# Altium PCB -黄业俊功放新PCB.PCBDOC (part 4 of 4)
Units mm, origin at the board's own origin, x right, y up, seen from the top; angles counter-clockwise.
Board outline 130 x 100.6 mm, 2 copper layers (Top Layer, Bottom Layer); 47 components, 24 nets, 117 pads, 4 vias.
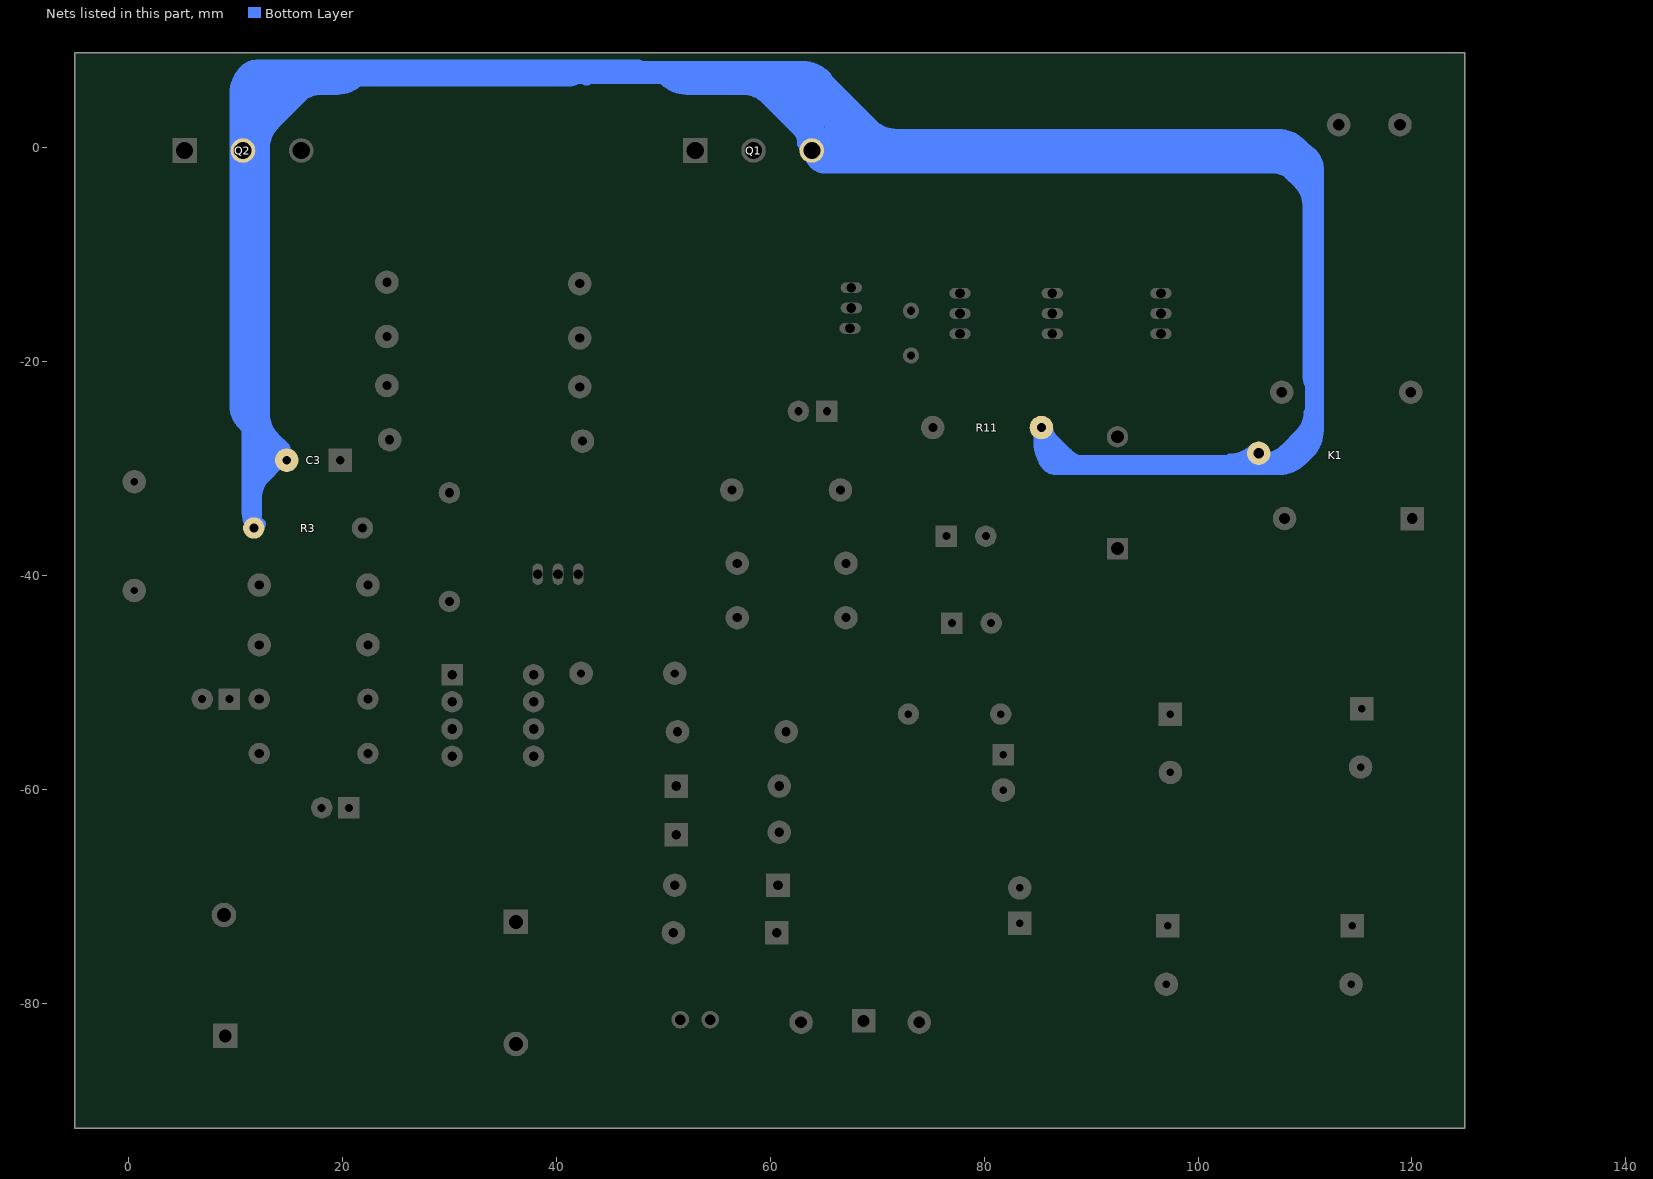
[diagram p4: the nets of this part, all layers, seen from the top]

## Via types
v1: diameter 2.54, hole 0.762, Top Layer to Bottom Layer, 4 vias

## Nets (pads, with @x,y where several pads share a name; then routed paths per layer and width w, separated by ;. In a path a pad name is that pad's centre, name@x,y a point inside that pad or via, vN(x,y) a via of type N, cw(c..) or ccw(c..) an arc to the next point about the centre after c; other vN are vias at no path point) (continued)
OUT: C3.2 K1.3 Q1.3 Q2.2 R3.2 R11.2 | length 1584.2
  Bottom Layer w1: 9.906,-24.13 ccw(c12.359,-24.13) 10.624,-25.864 10.786,-26.026 cw(c8.618,-28.194) 11.684,-28.194 11.684,-29.337 ; Q2.2@9.906,-0.381 10.259,-0.734 cw(c8.351,-2.642) 11.049,-2.642 11.049,-34.154 ccw(c13.217,-34.154) R3.2@11.684,-35.687 ; Q2.2@10.287,-0.381 10.287,-23.539 ccw(c12.021,-23.539) 10.795,-24.765 cw(c9.569,-25.991) 11.303,-25.991 11.303,-31.877 ; Q2.2@10.287,-0.254 10.287,4.69 cw(c12.455,4.69) 10.922,6.223 11.021,6.322 cw(c12.929,4.414) 12.929,7.112 62.001,7.112 cw(c62.001,4.414) 63.909,6.322 cw(c63.058,5.47) 64.262,5.47 Q1.3@64.262,-0.635 ; Q2.2@10.668,0.254 10.668,3.581 cw(c13.366,3.581) 11.458,5.489 11.529,5.56 cw(c13.437,3.652) 13.437,6.35 ; Q2.2@10.922,-0.381 10.922,1.549 cw(c13.62,1.549) 11.712,3.457 13.561,5.306 cw(c15.469,3.398) 15.469,6.096 ; Q2.2@11.049,-0.635 11.049,2.438 cw(c13.747,2.438) 11.839,4.346 13.18,5.687 cw(c15.088,3.779) 15.088,6.477 59.969,6.477 cw(c59.969,3.779) 61.877,5.687 62.583,4.981 cw(c60.675,3.073) 63.373,3.073 63.373,0.815 ccw(c63.807,0.815) 63.5,0.508 63.537,0.471 cw(c63.32,0.254) Q1.3@63.627,0.254 ; Q2.2@11.303,0.254 11.529,0.028 cw(c9.621,-1.88) 12.319,-1.88 12.319,-25.933 ccw(c15.017,-25.933) 13.109,-27.841 13.753,-28.485 ccw(c13.97,-28.268) C3.2@13.97,-28.575 ; Q2.2@11.43,-0.508 11.43,3.327 cw(c14.128,3.327) 12.22,5.235 12.291,5.306 cw(c14.199,3.398) 14.199,6.096 ; 11.557,-26.543 10.804,-25.79 cw(c12.972,-23.622) 9.906,-23.622 9.906,4.318 9.906,5.08 cw(c12.972,5.08) 10.804,7.248 cw(c12.009,6.043) 12.009,7.747 47.572,7.747 cw(c47.572,7.313) 47.879,7.62 62.992,7.62 cw(c62.992,4.554) 65.16,6.722 cw(c64.875,6.437) 65.278,6.437 65.278,3.237 ccw(c67.88,3.237) 66.04,1.397 ccw(c67.266,2.623) 67.266,0.889 107.709,0.889 cw(c107.709,-2.146) 109.855,0 110.258,-0.403 cw(c109.391,-1.27) 110.617,-1.27 ccw(c110.617,-2.19) 109.967,-1.539 ; Q2.2@11.557,0.381 11.557,2.819 cw(c14.255,2.819) 12.347,4.727 13.434,5.814 cw(c15.342,3.906) 15.342,6.604 60.477,6.604 cw(c60.477,3.906) 62.385,5.814 63.091,5.108 cw(c61.183,3.2) 63.881,3.2 Q1.3@63.881,0 ; R3.2@11.684,-35.179 11.684,-31.233 cw(c12.888,-31.233) 12.037,-30.381 cw(c13.945,-32.289) 13.945,-29.591 C3.2@14.351,-29.591 ; 11.684,-30.455 cw(c12.802,-30.455) 12.802,-29.337 C3.2@14.605,-29.337 ; 11.684,-25.781 11.684,-26.521 ccw(c14.189,-26.521) 12.418,-28.293 ccw(c14.326,-26.385) 14.326,-29.083 C3.2@14.478,-29.083 ; Q2.2@11.684,-0.635 11.684,-34.544 ccw(c12.319,-34.544) R3.2@12.319,-35.179 ; R3.2@11.938,-35.306 11.938,-32.741 cw(c14.636,-32.741) 12.728,-30.833 C3.2@13.97,-29.591 ; 11.938,-28.194 12.827,-29.083 ; 12.065,-1.27 12.065,1.016 cw(c15.131,1.016) 12.963,3.184 15.104,5.325 cw(c17.272,3.157) 17.272,6.223 41.065,6.223 ccw(c41.065,7.957) 42.291,6.731 42.586,6.436 ccw(c42.854,6.704) 42.854,6.325 cw(c43.833,5.346) 43.833,6.731 57.912,6.731 cw(c57.912,3.665) 60.08,5.833 61.967,3.946 cw(c59.799,1.778) 62.865,1.778 ccw(c65.931,1.778) 63.763,-0.39 Q1.3@64.516,-1.143 ; 12.192,-4.699 12.192,2.819 cw(c14.89,2.819) 12.982,4.727 13.815,5.56 cw(c15.723,3.652) 15.723,6.35 17.653,6.35 ; 12.319,-1.651 12.319,0.508 cw(c15.385,0.508) 13.217,2.676 16.247,5.706 cw(c18.415,3.538) 18.415,6.604 20.828,6.604 ; 12.319,3.302 ccw(c12.319,3.609) 12.536,3.392 15.113,5.969 ; 12.7,2.667 ccw(c12.7,5.733) 14.868,3.565 15.866,4.563 cw(c18.034,2.395) 18.034,5.461 19.444,5.461 ccw(c19.444,8.496) 21.59,6.35 ; C3.2@14.859,-28.956 cw(c15.472,-28.343) 14.605,-28.343 14.605,-28.067 13.598,-27.06 cw(c15.766,-24.892) 12.7,-24.892 12.7,0 cw(c15.766,0) 13.598,2.168 17.136,5.706 cw(c19.304,3.538) 19.304,6.604 22.479,6.604 ; 16.256,6.731 60.604,6.731 cw(c60.604,4.033) 62.512,5.941 62.837,5.616 cw(c60.929,3.708) 63.627,3.708 63.627,2.466 ccw(c64.061,2.466) 63.754,2.159 ; 49.784,6.858 57.15,6.858 cw(c57.15,3.792) 59.318,5.96 62.998,2.28 cw(c61.481,0.762) 63.627,0.762 cw(c63.627,-0.771) 64.711,0.313 ccw(c66.08,1.682) 66.08,-0.254 68.729,-0.254 ccw(c68.729,0.613) 69.342,0 cw(c69.955,-0.613) 69.955,0.254 67.118,0.254 cw(c67.118,2.856) 65.278,1.016 64.389,1.905 ccw(c64.082,2.212) 64.516,2.212 64.516,6.35 ; 49.911,6.477 50.029,6.359 ccw(c52.197,8.527) 52.197,5.461 57.404,5.461 cw(c57.404,2.395) 59.572,4.563 62.475,1.66 cw(c60.307,-0.508) Q1.3@63.373,-0.508 ; 50.419,6.223 ccw(c51.339,7.143) 51.339,5.842 58.039,5.842 ; 51.308,6.731 56.515,6.731 cw(c56.515,3.665) 58.683,5.833 62.184,2.332 cw(c60.233,0.381) 62.992,0.381 63.373,0.381 cw(c63.373,-2.685) 65.541,-0.517 66.077,-1.053 ccw(c66.294,-0.836) 66.294,-1.143 66.294,-1.016 ; 53.975,6.477 58.674,6.477 cw(c58.674,3.411) 60.842,5.579 61.976,4.445 ; 60.071,6.731 ccw(c60.071,7.038) 60.288,6.821 60.325,6.858 60.833,6.858 cw(c60.833,3.792) 63.001,5.96 63.246,5.715 ccw(c63.859,6.328) 63.859,5.461 64.77,5.461 ; 60.223,6.096 cw(c60.223,3.398) 62.131,5.306 62.456,4.981 cw(c60.548,3.073) 63.246,3.073 Q1.3@63.246,0.254 ; 61.341,5.461 63.447,3.355 cw(c63.014,2.921) 63.627,2.921 ; 62.072,6.35 cw(c62.072,5.049) 62.992,5.969 63.091,5.87 cw(c61.183,3.962) 63.881,3.962 Q1.3@63.881,0.127 ; Q1.3@63.119,0.127 63.726,-0.48 ccw(c65.634,1.428) 65.634,-1.27 107.467,-1.27 cw(c107.467,-3.968) 109.375,-2.06 109.954,-2.639 cw(c108.046,-4.547) 110.744,-4.547 110.744,-7.366 ; 63.119,7.239 63.246,7.239 cw(c63.246,4.173) 65.414,6.341 69.587,2.168 ccw(c71.755,4.336) 71.755,1.27 107.442,1.27 cw(c107.442,-1.796) 109.61,0.372 110.49,-0.508 110.49,-0.657 cw(c109.623,-0.657) 110.236,-1.27 110.109,-1.397 ; Q1.3@63.373,-0.254 107.179,-0.254 cw(c107.179,-2.422) 108.712,-0.889 109.7,-1.877 cw(c107.792,-3.785) 110.49,-3.785 110.49,-10.033 ; Q1.3@63.5,0 ccw(c65.646,0) 64.129,-1.518 ccw(c65.064,-0.582) 65.064,-1.905 106.959,-1.905 cw(c106.959,-4.603) 108.867,-2.695 109.446,-3.274 cw(c107.538,-5.182) 110.236,-5.182 110.236,-6.35 ; 63.627,7.239 cw(c63.627,6.932) 63.844,7.149 64.77,6.223 ; Q1.3@63.754,-0.381 107.467,-0.381 cw(c107.467,-3.079) 109.375,-1.171 109.827,-1.623 cw(c107.919,-3.531) 110.617,-3.531 110.617,-7.62 ; 63.754,4.699 cw(c63.754,4.392) 63.971,4.609 67.682,0.898 ccw(c69.85,3.066) 69.85,0 72.771,0 ; Q1.3@64.389,0.127 107.975,0.127 cw(c107.975,-2.571) 109.883,-0.663 110.335,-1.115 cw(c108.427,-3.023) 111.125,-3.023 111.125,-3.556 ccw(c110.818,-3.249) 111.252,-3.249 111.252,-2.001 ccw(c109.18,-2.001) 110.645,-0.536 ccw(c108.737,-2.444) 108.737,0.254 106.045,0.254 ; 73.66,-0.508 ccw(c73.047,-1.121) 73.047,-0.254 71.12,-0.254 cw(c71.12,2.812) 68.952,0.644 68.326,1.27 65.219,4.377 cw(c66.303,5.461) 64.77,5.461 ; 74.676,0.762 70.866,0.762 cw(c70.866,3.828) 68.698,1.66 64.987,5.371 ccw(c64.77,5.154) 64.77,5.461 ; R11.2@85.087,-26.704 cw(c84.798,-27.312) 85.471,-27.312 ; 85.09,-27.594 cw(c86.118,-27.594) R11.2@85.629,-26.69 ; R11.2@85.09,-26.035 85.09,-27.572 ccw(c88.125,-27.572) 85.979,-29.718 ccw(c86.592,-29.105) 86.592,-29.972 89.482,-29.972 ccw(c89.482,-29.538) 89.789,-29.845 ; R11.2@85.344,-26.762 cw(c85.344,-28.211) 86.368,-27.186 cw(c87.393,-26.162) R11.2@85.944,-26.162 ; R11.2@85.344,-26.035 85.344,-26.188 ccw(c88.348,-26.188) 86.224,-28.312 ccw(c88.392,-26.144) 88.392,-29.21 106.299,-29.21 ccw(c106.299,-26.144) 108.467,-28.312 109.855,-26.924 ccw(c107.709,-24.778) 110.744,-24.778 110.744,-18.796 ; R11.2@85.344,-25.781 ccw(c88.41,-25.781) 86.242,-27.949 86.732,-28.439 ccw(c88.9,-26.271) 88.9,-29.337 90.424,-29.337 ; R11.2@85.471,-26.289 87.748,-28.566 ccw(c89.916,-26.398) 89.916,-29.464 91.567,-29.464 ; R11.2@85.471,-25.908 85.471,-28.47 ccw(c86.338,-28.47) 85.725,-29.083 ccw(c87.258,-27.55) 87.258,-29.718 106.807,-29.718 ccw(c106.807,-27.572) 108.325,-29.089 110.354,-27.06 ccw(c108.186,-24.892) 111.252,-24.892 111.252,-1.905 ; 97.917,-0.381 107.721,-0.381 cw(c107.721,-3.079) 109.629,-1.171 109.954,-1.496 cw(c108.046,-3.404) 110.744,-3.404 110.744,-5.715 ; 100.536,-30.099 ccw(c100.536,-23.447) K1.3@105.24,-28.151 ; 100.838,-1.524 106.451,-1.524 cw(c106.451,-4.222) 108.359,-2.314 109.446,-3.401 cw(c107.538,-5.309) 110.236,-5.309 110.236,-21.253 ccw(c111.97,-21.253) 110.744,-22.479 ; 101.456,-29.718 ccw(c101.456,-24.367) K1.3@105.24,-28.151 ; 102.682,-29.21 ccw(c102.682,-25.593) K1.3@105.24,-28.151 ; 102.95,-30.099 ccw(c102.95,-25.861) 105.947,-28.858 cw(c103.87,-26.781) 103.87,-29.718 ; 104.013,-1.27 107.34,-1.27 cw(c107.34,-3.968) 109.248,-2.06 109.7,-2.512 cw(c107.792,-4.42) 110.49,-4.42 110.49,-8.382 ; K1.3@105.156,-28.194 cw(c105.156,-28.829) K1.3@105.791,-28.829 ; K1.3@105.239,-28.152 cw(c102.997,-25.92) 102.997,-29.083 105.918,-29.083 ccw(c105.918,-26.017) 108.086,-28.185 109.555,-26.716 ccw(c107.604,-24.765) 110.363,-24.765 ccw(c109.443,-23.845) 110.744,-23.845 110.744,-23.368 ; K1.3@105.532,-29.083 cw(c104.419,-28.981) 104.419,-30.099 86.741,-30.099 cw(c86.741,-28.829) 85.471,-28.829 85.471,-26.162 85.471,-27.305 ccw(c88.537,-27.305) 86.369,-29.473 ccw(c87.88,-27.962) 87.88,-30.099 92.964,-30.099 107.569,-30.099 ccw(c107.569,-27.033) 109.737,-29.201 110.354,-28.584 ccw(c108.186,-26.416) 111.252,-26.416 111.252,-22.733 111.252,-8.509 ; K1.3@105.664,-28.321 105.664,-29.972 ; 106.045,-29.972 107.315,-29.972 ccw(c107.315,-26.906) 109.483,-29.074 110.354,-28.203 ccw(c108.186,-26.035) 111.252,-26.035 111.252,-6.604 ; 107.188,-29.845 ccw(c107.188,-26.779) 109.356,-28.947 110.49,-27.813 110.49,-4.953 ; 108.585,-29.464 cw(c109.505,-29.464) 108.854,-28.814 110.49,-27.178 ccw(c109.264,-25.952) 110.998,-25.952 110.998,-5.461 ; 110.49,-8.509 110.49,-5.842 ; 111.252,-14.986 111.252,-6.477 ; 111.252,-11.43 111.252,-2.007 ; 111.252,-6.858 111.252,-2.032 ; R11.2@84.92,-26.586 cw(c83.589,-27.917) 85.471,-27.917 ; R11.2@84.92,-26.586 cw(c83.589,-27.917) 85.471,-27.917 ; R11.2@84.92,-26.586 cw(c83.895,-27.611) 85.344,-27.611 ; R11.2@84.92,-26.586 cw(c83.895,-27.611) 85.344,-27.611 ; R11.2@84.92,-26.586 cw(c83.895,-27.611) 85.344,-27.611 ; R11.2@84.92,-26.586 cw(c83.589,-27.917) 85.471,-27.917 ; 85.344,-27.611 cw(c86.793,-27.611) R11.2@85.768,-26.586 ; 85.344,-27.611 cw(c86.793,-27.611) R11.2@85.768,-26.586 ; 85.344,-27.611 cw(c86.793,-27.611) R11.2@85.768,-26.586 ; 85.471,-27.304 cw(c86.486,-27.304) R11.2@85.768,-26.586 ; 85.471,-27.304 cw(c86.486,-27.304) R11.2@85.768,-26.586 ; 85.471,-27.304 cw(c86.486,-27.304) R11.2@85.768,-26.586 ; 85.471,-27.304 cw(c86.486,-27.304) R11.2@85.768,-26.586 ; 105.664,-29.972 cw(c106.99,-29.972) 106.077,-29.01 ccw(c106.99,-29.972) 105.664,-29.972 ; 105.664,-29.972 ccw(c104.338,-29.972) 105.251,-29.01 cw(c104.338,-29.972) 105.664,-29.972
pads on no net: K1.2 U.5 U.6 U.7
copper on no net:
  other v1: 26.67,3.81 43.053,4.064 73.279,4.064 -3.048,4.318

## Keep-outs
Keep-Out Layer:
  the board outline again, w0.3

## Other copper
Bottom Layer:
  rectangle net GND: 100.33,-82.677 110.871,-73.533
  rectangle net GND: 86.995,-82.296 93.599,-68.58
  rectangle net GND: 80.899,-23.368 105.156,-19.685
  rectangle net GND: 78.232,-32.004 83.185,-20.32
  rectangle net GND: 95.885,-46.228 104.648,-32.385
  rectangle net GND: 7.747,-88.265 37.719,-80.772
  rectangle net GND: -0.889,-86.741 5.715,-69.596
  rectangle net GND: 81.407,-69.215 96.52,-59.69
  rectangle net GND: 93.853,-72.644 124.079,-56.896
  text "Deidre_141806048" at 79.502,4.445 h1.52
  text "2016-4-15" at 17.78,-20.066 h1.52 r90

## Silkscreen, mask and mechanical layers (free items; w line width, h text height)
Top Overlay:
  circle w0.254: c36.085,-78.105 r11.286
  circle w0.254: c9.034,-77.47 r11.286
Drill Drawing:
  text ".LEGEND" at 130,-86.614 h0.65
  text "Drill Drawing." at 130,-89.154 h0.65

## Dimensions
-5.08,-91.694 to -5.08,8.906 on Mechanical 1
-5.08,-91.694 to 124.92,-91.694 on Mechanical 1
